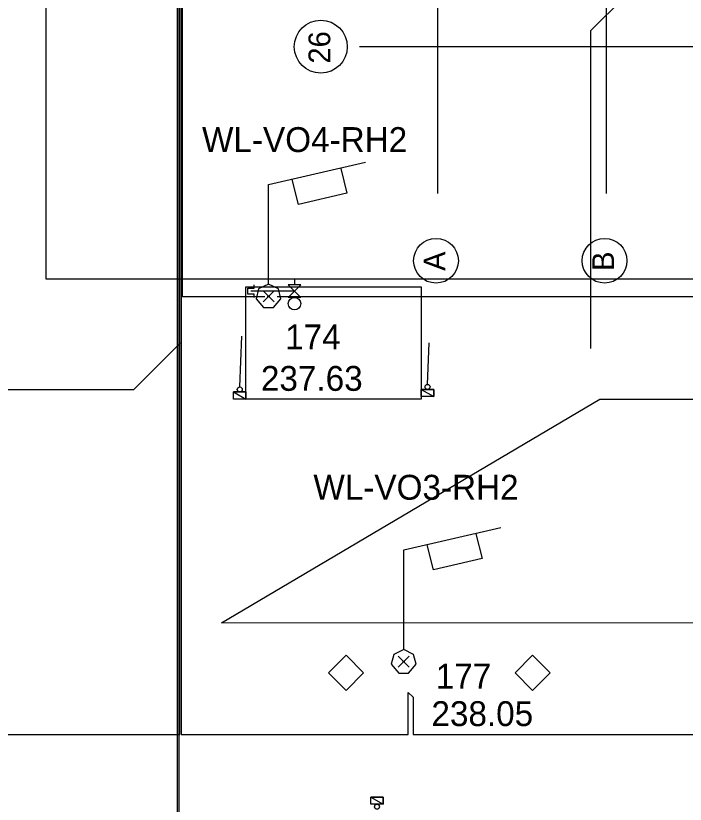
# Model space of a CAD drawing. Extents: x -264222 to -263592, y -1242345 to -1242048.
# Drawn here: x -263925.35 to -263898.44, y -1242271.27 to -1242239.56 of the extents above; entities that cross this region are included whole.
import ezdxf

# ---------------------------------------------------------------- set-up
doc = ezdxf.new("R2010")
doc.units = 0
for name, color, linetype in [('BOD_CISLO', 7, 'Continuous'), ('BOD_SYMBOL', 7, 'Continuous'), ('BOD_VYSKA', 7, 'Continuous'), ('HESCON_OSI_STAVBY_KFA', 7, 'Continuous'), ('KFA_2D_SITUACIA_DSP', 7, 'Continuous'), ('KFA_SO_62-1_VO_LAMPY_MERANE', 7, 'Continuous'), ('KFA_SO_62-1_VO_POPIS_LAMP_PROJEKT', 7, 'Continuous'), ('KFA_SO_62-1_VO_TRASA_KABLOV_PROJEKT', 7, 'Continuous')]:
    doc.layers.add(name, color=color, linetype=linetype)

msp = doc.modelspace()

# ---------------------------------------------------------------- linework, layer by layer
at = {"layer": 'BOD_SYMBOL'}
for p, q in [((-263915.406, -1242251.072), (-263914.964, -1242250.63)), ((-263914.964, -1242251.072), (-263915.406, -1242250.63)), ((-263909.974, -1242265.766), (-263909.532, -1242265.324)), ((-263909.532, -1242265.766), (-263909.974, -1242265.324))]:
    msp.add_line(p, q, dxfattribs=at)
at = {"layer": 'HESCON_OSI_STAVBY_KFA'}
for p, q in [((-263908.393, -1242083.237), (-263908.393, -1242246.707)), ((-263901.618, -1242083.237), (-263901.618, -1242246.707)), ((-263792.653, -1242240.807), (-263911.523, -1242240.807))]:
    msp.add_line(p, q, dxfattribs=at)
for centre, radius in [((-263913.085, -1242240.807), 1.064), ((-263908.453, -1242249.416), 0.899), ((-263901.678, -1242249.416), 0.899)]:
    msp.add_circle(centre, radius, dxfattribs=at)
at = {"layer": 'KFA_2D_SITUACIA_DSP'}
for p, q in [((-263924.143, -1242185.14), (-263924.143, -1242250.14)), ((-263898.965, -1242236.895), (-263902.238, -1242240.168)), ((-263899.018, -1242236.948), (-263902.238, -1242240.168)), ((-263902.238, -1242240.168), (-263902.238, -1242252.949)), ((-263924.143, -1242250.14), (-263788.143, -1242250.14)), ((-263914.143, -1242250.14), (-263914.143, -1242250.39)), ((-263914.143, -1242250.14), (-263914.143, -1242250.39)), ((-263916.093, -1242254.982), (-263916.093, -1242250.458)), ((-263916.093, -1242250.458), (-263909.043, -1242250.458)), ((-263916.018, -1242250.515), (-263915.768, -1242250.515)), ((-263916.018, -1242250.765), (-263916.018, -1242250.515)), ((-263914.143, -1242250.64), (-263915.893, -1242250.64)), ((-263915.768, -1242250.515), (-263915.768, -1242250.39)), ((-263914.393, -1242250.39), (-263913.893, -1242250.89)), ((-263913.893, -1242250.39), (-263914.393, -1242250.39)), ((-263914.393, -1242250.89), (-263913.893, -1242250.39)), ((-263909.043, -1242250.458), (-263909.043, -1242254.982)), ((-263915.768, -1242250.765), (-263916.018, -1242250.765)), ((-263915.768, -1242250.89), (-263915.768, -1242250.765)), ((-263913.893, -1242250.89), (-263914.393, -1242250.89)), ((-263916.339, -1242254.492), (-263916.265, -1242252.443)), ((-263920.595, -1242254.592), (-263918.723, -1242252.72)), ((-263908.789, -1242254.387), (-263908.729, -1242252.715)), ((-263929.73, -1242254.592), (-263920.595, -1242254.592)), ((-263916.593, -1242254.692), (-263916.093, -1242254.692)), ((-263916.593, -1242254.982), (-263916.593, -1242254.692)), ((-263916.593, -1242254.692), (-263916.093, -1242254.982)), ((-263916.593, -1242254.692), (-263916.093, -1242254.982)), ((-263916.093, -1242254.692), (-263916.593, -1242254.692)), ((-263916.093, -1242254.692), (-263916.093, -1242254.982)), ((-263916.093, -1242254.982), (-263916.093, -1242254.692)), ((-263909.043, -1242254.587), (-263908.543, -1242254.587)), ((-263909.043, -1242254.877), (-263909.043, -1242254.587)), ((-263909.043, -1242254.587), (-263908.543, -1242254.877)), ((-263909.043, -1242254.587), (-263908.543, -1242254.877)), ((-263908.543, -1242254.587), (-263909.043, -1242254.587)), ((-263908.543, -1242254.587), (-263908.543, -1242254.877)), ((-263908.543, -1242254.877), (-263908.543, -1242254.587)), ((-263916.093, -1242254.982), (-263916.593, -1242254.982)), ((-263909.043, -1242254.982), (-263916.093, -1242254.982)), ((-263908.543, -1242254.877), (-263909.043, -1242254.877)), ((-263911.074, -1242270.983), (-263910.574, -1242270.983)), ((-263911.074, -1242271.273), (-263911.074, -1242270.983)), ((-263911.074, -1242270.983), (-263910.574, -1242271.273)), ((-263911.074, -1242270.983), (-263910.574, -1242271.273)), ((-263910.574, -1242270.983), (-263911.074, -1242270.983)), ((-263910.574, -1242271.273), (-263911.074, -1242271.273)), ((-263910.574, -1242270.983), (-263910.574, -1242271.273)), ((-263910.574, -1242271.273), (-263910.574, -1242270.983))]:
    msp.add_line(p, q, dxfattribs=at)
msp.add_lwpolyline([(-263854.468, -1242263.985), (-263917.08, -1242263.982), (-263901.868, -1242254.982), (-263854.468, -1242254.985), (-263854.468, -1242263.985)], dxfattribs=at)
for points in [[(-263912.068, -1242265.279), (-263911.361, -1242265.986), (-263912.068, -1242266.693), (-263912.775, -1242265.986)], [(-263904.568, -1242265.279), (-263903.861, -1242265.986), (-263904.568, -1242266.693), (-263905.275, -1242265.986)]]:
    msp.add_lwpolyline(points, close=True, dxfattribs=at)
for centre, radius in [((-263914.143, -1242251.14), 0.25), ((-263916.343, -1242254.592), 0.1), ((-263908.793, -1242254.487), 0.1), ((-263910.824, -1242271.373), 0.1)]:
    msp.add_circle(centre, radius, dxfattribs=at)
at = {"layer": 'KFA_SO_62-1_VO_LAMPY_MERANE'}
for p, q in [((-263915.235, -1242250.851), (-263915.135, -1242250.851)), ((-263915.185, -1242250.851), (-263915.185, -1242250.851)), ((-263909.803, -1242265.545), (-263909.703, -1242265.545)), ((-263909.753, -1242265.545), (-263909.753, -1242265.545))]:
    msp.add_line(p, q, dxfattribs=at)
for points in [[(-263915.185, -1242250.351), (-263915.585, -1242250.551), (-263915.685, -1242250.951), (-263915.385, -1242251.301), (-263914.985, -1242251.301), (-263914.685, -1242250.951), (-263914.785, -1242250.551), (-263915.185, -1242250.351), (-263915.185, -1242246.351), (-263911.285, -1242245.451)], [(-263912.285, -1242245.701), (-263912.035, -1242246.701), (-263913.985, -1242247.151), (-263914.235, -1242246.151)], [(-263909.753, -1242265.045), (-263910.153, -1242265.245), (-263910.253, -1242265.645), (-263909.953, -1242265.995), (-263909.553, -1242265.995), (-263909.253, -1242265.645), (-263909.353, -1242265.245), (-263909.753, -1242265.045), (-263909.753, -1242261.045), (-263905.853, -1242260.145)], [(-263906.853, -1242260.395), (-263906.603, -1242261.395), (-263908.553, -1242261.845), (-263908.803, -1242260.845)]]:
    msp.add_lwpolyline(points, dxfattribs=at)
at = {"layer": 'KFA_SO_62-1_VO_TRASA_KABLOV_PROJEKT'}
for p, q in [((-263918.845, -1242300.4), (-263918.845, -1242195.1)), ((-263918.795, -1242195.15), (-263918.795, -1242300.4)), ((-263918.745, -1242268.464), (-263918.745, -1242195.2)), ((-263918.695, -1242195.25), (-263918.695, -1242268.464)), ((-263918.638, -1242250.863), (-263918.645, -1242195.3)), ((-263915.338, -1242250.863), (-263918.638, -1242250.863)), ((-263895.838, -1242250.863), (-263914.838, -1242250.863)), ((-263909.568, -1242268.464), (-263909.568, -1242266.774)), ((-263909.568, -1242266.774), (-263909.374, -1242266.973)), ((-263909.374, -1242266.973), (-263909.374, -1242268.463)), ((-263938.934, -1242268.464), (-263918.745, -1242268.464)), ((-263918.695, -1242268.464), (-263909.568, -1242268.464)), ((-263909.374, -1242268.463), (-263892.068, -1242268.463))]:
    msp.add_line(p, q, dxfattribs=at)

# ---------------------------------------------------------------- texts
at = {"layer": 'BOD_CISLO'}
for s, p in [('174', (-263914.517, -1242252.979)), ('177', (-263908.462, -1242266.621))]:
    msp.add_text(s, height=1, dxfattribs=at).set_placement(p)
at = {"layer": 'BOD_VYSKA'}
for s, p in [('237.63', (-263915.491, -1242254.647)), ('238.05', (-263908.637, -1242268.13))]:
    msp.add_text(s, height=1, dxfattribs=at).set_placement(p)
at = {"layer": 'HESCON_OSI_STAVBY_KFA'}
for s, p in [('26', (-263912.704, -1242241.487)), ('A', (-263908.072, -1242249.824)), ('B', (-263901.297, -1242249.824))]:
    msp.add_text(s, height=0.875, rotation=90, dxfattribs=at).set_placement(p)
at = {"layer": 'KFA_SO_62-1_VO_POPIS_LAMP_PROJEKT'}
for s, p in [('WL-VO4-RH2', (-263917.858, -1242245.043)), ('WL-VO3-RH2', (-263913.381, -1242259.025))]:
    msp.add_text(s, height=1, dxfattribs=at).set_placement(p)

doc.saveas('drawing.dxf')
